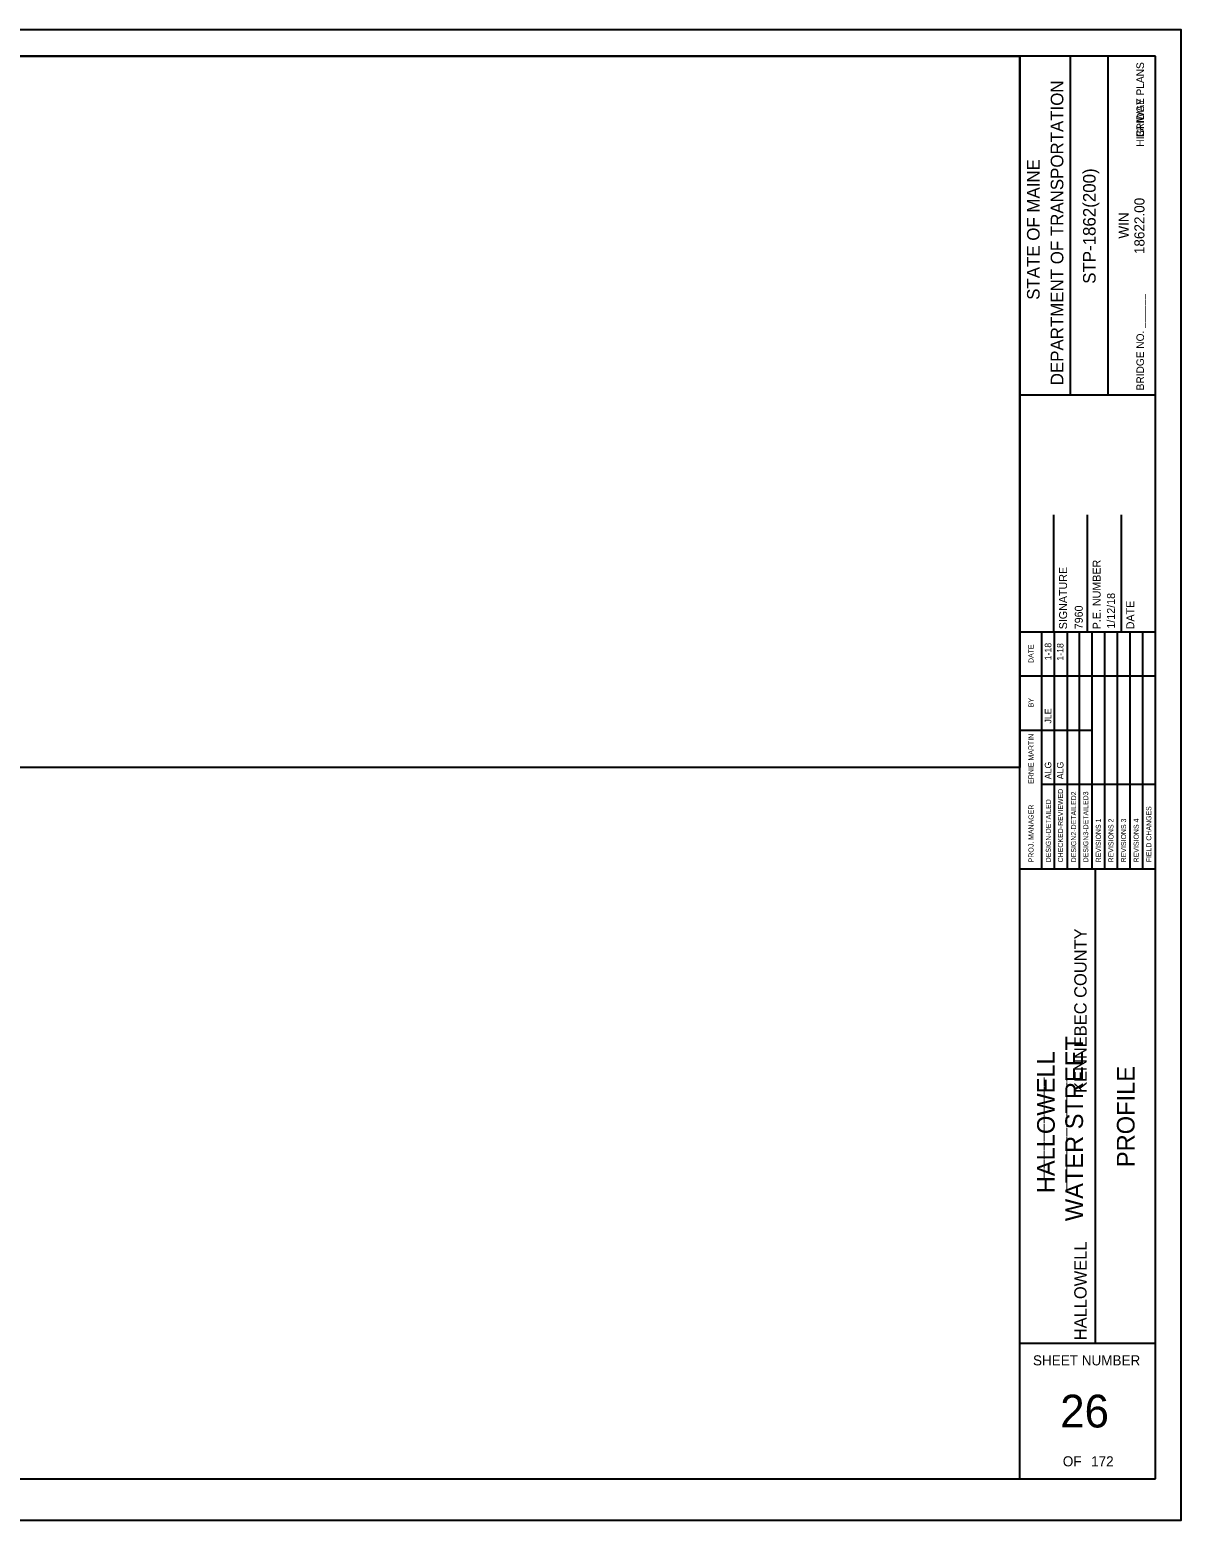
# Model space of a CAD drawing. Extents: x 0 to 850, y 0 to 550.
# Drawn here: x 425 to 850, y 0 to 550 of the extents above; entities that cross this region are included whole.
import ezdxf

# ---------------------------------------------------------------- set-up
doc = ezdxf.new("R2010")
doc.units = 0
for name, color, linetype in [('BORDER', 7, 'Continuous'), ('BRIDGE_TITLE', 7, 'Continuous'), ('Default', 7, 'Continuous'), ('HIGHWAY_TITLE', 7, 'Continuous'), ('PLOT BOUNDARY', 7, 'Continuous')]:
    doc.layers.add(name, color=color, linetype=linetype)

msp = doc.modelspace()

# ---------------------------------------------------------------- linework, layer by layer
at = {"layer": 'BORDER'}
for p, q in [((840.5, 540.32), (40.47, 540.32)), ((790.49, 15.32), (790.49, 540.33)), ((809.14, 415.3), (809.14, 540.3)), ((823.11, 415.3), (823.11, 540.3)), ((840.5, 15.32), (840.5, 540.32)), ((790.5, 415.29), (840.5, 415.29)), ((802.99, 327.83), (802.99, 371.07)), ((815.5, 327.83), (815.5, 371.07)), ((828, 327.83), (828, 371.07)), ((790.49, 327.83), (840.5, 327.83)), ((790.49, 240.33), (840.5, 240.33)), ((818.45, 65.32), (818.45, 240.33)), ((790.49, 65.32), (840.5, 65.32)), ((40.47, 15.3), (840.5, 15.3))]:
    msp.add_line(p, q, dxfattribs=at)
for points in [[(798.57, 311.58), (798.57, 327.83)], [(803.23, 240.34), (803.23, 327.83)], [(807.89, 327.83), (807.89, 240.34)], [(812.55, 240.34), (812.55, 327.83)], [(817.21, 240.34), (817.21, 327.83)], [(821.87, 240.34), (821.87, 327.83)], [(826.52, 240.34), (826.52, 327.83)], [(831.18, 240.34), (831.18, 327.83)], [(835.84, 240.34), (835.84, 327.83)], [(798.57, 240.34), (798.57, 324.3)], [(790.49, 311.58), (840.5, 311.58)], [(790.49, 291.58), (798.57, 291.58)], [(798.57, 291.58), (817.2, 291.58)], [(798.57, 271.58), (840.5, 271.58)]]:
    msp.add_lwpolyline(points, dxfattribs=at)
at = {"layer": 'Default'}
for points in [[(790.49, 277.83), (68.66, 277.83), (68.66, 540.32), (790.49, 540.32)], [(40.47, 15.3), (790.49, 15.3), (790.49, 277.83), (40.47, 277.83)]]:
    msp.add_lwpolyline(points, close=True, dxfattribs=at)
at = {"layer": 'PLOT BOUNDARY'}
msp.add_lwpolyline([(0, 0.01), (850.03, 0.01), (850.03, 550.02), (0, 550.02)], close=True, dxfattribs=at)

# ---------------------------------------------------------------- texts
at = {"layer": 'BORDER'}
for s, height, p in [('DEPARTMENT OF TRANSPORTATION', 4.6589, (806.53, 418.85)), ('STATE OF MAINE', 4.6589, (797.77, 450.38)), ('STP-1862(200)', 4.6589, (818.45, 456.29)), ('18622.00', 3.726, (836.47, 467.25)), ('WIN', 3.726, (830.68, 472.97)), ('P.E. NUMBER', 2.9528, (820.3, 328.79)), ('SIGNATURE', 2.953, (807.9, 328.79)), ('1/12/18', 2.953, (825.6, 329.03)), ('7960', 2.953, (813.7, 328.79)), ('DATE', 2.953, (832.7, 328.79)), ('DATE', 1.857, (795.52, 316.36)), ('1-18', 2.423, (802.11, 317.32)), ('1-18', 2.423, (806.58, 317.2)), ('BY', 1.857, (795.52, 300)), ('JLE', 2.423, (802.11, 294)), ('ERNIE MARTIN', 1.8638, (795.52, 271.78)), ('ALG', 2.423, (802.11, 273.44)), ('ALG', 2.423, (806.58, 273.44)), ('DESIGN-DETAILED', 1.8638, (801.93, 242.77)), ('CHECKED-REVIEWED', 1.8638, (806.4, 242.77)), ('DESIGN2-DETAILED2', 1.8638, (811.24, 242.77)), ('DESIGN3-DETAILED3', 1.8638, (815.72, 242.77)), ('PROJ. MANAGER', 1.8638, (795.52, 242.77)), ('FIELD CHANGES', 1.8638, (839.01, 242.77)), ('REVISIONS 1', 1.8638, (820.38, 242.77)), ('REVISIONS 2', 1.8638, (825.03, 242.77)), ('REVISIONS 3', 1.8638, (829.69, 242.77)), ('REVISIONS 4', 1.8638, (834.35, 242.77)), ('PROFILE', 6.522, (832.82, 130.31))]:
    msp.add_text(s, height=height, rotation=90, dxfattribs=at).set_placement(p)
for s, height, p in [('SHEET NUMBER', 3.7265, (795.32, 57.14)), ('26', 12.097, (805.37, 34.22)), ('OF', 3.726, (806.33, 19.87)), ('172', 3.726, (816.78, 19.87))]:
    msp.add_text(s, height=height, dxfattribs=at).set_placement(p)
at = {"layer": 'BRIDGE_TITLE'}
for s, height, p in [('BRIDGE PLANS', 2.7951, (836.29, 510.44)), ('BRIDGE NO. ______', 2.7951, (836.29, 416.97)), ('KENNEBEC COUNTY', 4.5359, (815.1, 157.71)), ('_____________', 4.5359, (806.71, 121.26)), ('___________', 4.5359, (798.33, 126.24)), ('HALLOWELL', 4.536, (815.1, 66.43))]:
    msp.add_text(s, height=height, rotation=90, dxfattribs=at).set_placement(p)
at = {"layer": 'HIGHWAY_TITLE'}
for s, height, p in [('HIGHWAY PLANS', 2.7951, (836.29, 506.89)), ('WATER STREET', 6.5216, (813.79, 110.36)), ('HALLOWELL', 6.522, (803.36, 120.69))]:
    msp.add_text(s, height=height, rotation=90, dxfattribs=at).set_placement(p)

doc.saveas('drawing.dxf')
